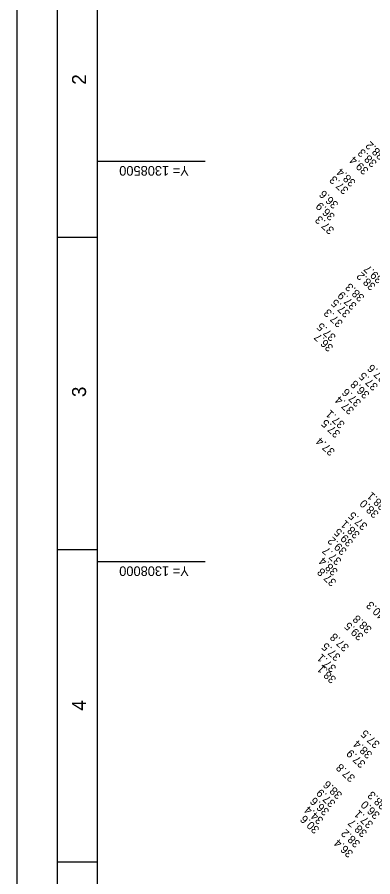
# Model space of a CAD drawing. Extents: x 515576 to 518976, y 1305110 to 1309511.
# Drawn here: x 515576 to 516021, y 1307607 to 1308680 of the extents above; entities that cross this region are included whole.
import ezdxf

# ---------------------------------------------------------------- set-up
doc = ezdxf.new("R2010")
doc.units = 0
for name, color, linetype in [('G-ANNO-NPLT', 7, 'Continuous'), ('G-ANNO-TTLB', 7, 'Continuous'), ('V-TOPO-COOR-STAT', 7, 'Continuous'), ('V-TOPO-SOUN', 7, 'Continuous')]:
    doc.layers.add(name, color=color, linetype=linetype)

msp = doc.modelspace()

# ---------------------------------------------------------------- linework, layer by layer
at = {"layer": 'G-ANNO-NPLT'}
msp.add_lwpolyline([(515576.5, 1305110.5), (515576.5, 1309510.4), (518976.4, 1309510.4), (518976.4, 1305110.5)], close=True, dxfattribs=at)
at = {"layer": 'G-ANNO-TTLB'}
for p, q in [((515626.5, 1308405.4), (515676.5, 1308405.4)), ((515626.5, 1308015.4), (515676.5, 1308015.4)), ((515626.5, 1307625.4), (515676.5, 1307625.4))]:
    msp.add_line(p, q, dxfattribs=at)
for points in [[(518926.4, 1305160.5), (518926.4, 1309460.4), (515626.5, 1309460.4), (515626.5, 1305160.5)], [(515676.5, 1309410.4), (515676.5, 1305285.5), (518876.4, 1305285.5), (518876.4, 1309410.4)]]:
    msp.add_lwpolyline(points, close=True, dxfattribs=at)
at = {"layer": 'V-TOPO-COOR-STAT'}
for p, q in [((515811.5, 1308500), (515676.5, 1308500)), ((515811.5, 1308000), (515676.5, 1308000))]:
    msp.add_line(p, q, dxfattribs=at)

# ---------------------------------------------------------------- texts
at = {"layer": 'G-ANNO-TTLB'}
for s, p in [('2', (515662.6, 1308595.9)), ('3', (515662.6, 1308205.8)), ('4', (515662.6, 1307814.1))]:
    msp.add_text(s, height=17.5, rotation=90, dxfattribs=at).set_placement(p)
at = {"layer": 'V-TOPO-COOR-STAT'}
for s, p in [('Y= 1308500', (515791.1, 1308494.3)), ('Y= 1308000', (515791.1, 1307994.3))]:
    msp.add_text(s, height=12, rotation=180, dxfattribs=at).set_placement(p)
at = {"layer": 'V-TOPO-SOUN'}
for s, p in [('38.2 ', (516036.9, 1308508.1)), ('38.3 ', (516027.2, 1308498.9)), ('39.4 ', (516016.8, 1308489.6)), ('38.4 ', (516000.7, 1308474.6)), ('37.3 ', (515991.8, 1308465.1)), ('36.6 ', (515979, 1308447.1)), ('36.9 ', (515974.8, 1308432.3)), ('37.3 ', (515973.8, 1308415.2)), ('39.7 ', (516034.7, 1308353.8)), ('38.2 ', (516025.7, 1308345.1)), ('38.3 ', (516011.6, 1308331)), ('37.9 ', (516002, 1308320.8)), ('37.5 ', (515993.8, 1308311.2)), ('37.3 ', (515984.7, 1308298.9)), ('37.5 ', (515975.9, 1308281.6)), ('36.7 ', (515972.6, 1308268.6)), ('37.6 ', (516039.2, 1308229.8)), ('37.5 ', (516028.6, 1308219.9)), ('36.8 ', (516018, 1308209.8)), ('37.6 ', (516007.5, 1308199.7)), ('37.4 ', (515998.7, 1308190.1)), ('37.1 ', (515987.1, 1308172.7)), ('37.5 ', (515981.5, 1308161)), ('37.4 ', (515974.8, 1308138.5)), ('38.1 ', (516038.7, 1308070.3)), ('38.0 ', (516029.6, 1308060.8)), ('37.5 ', (516015.4, 1308045.6)), ('38.1 ', (516005.9, 1308035)), ('39.5 ', (515997.5, 1308025)), ('39.2 ', (515989.6, 1308014.4)), ('37.7 ', (515982.9, 1308001.9)), ('38.4 ', (515978.4, 1307988.8)), ('37.8 ', (515976.5, 1307975.4)), ('40.3 ', (516037.8, 1307933.7)), ('38.8 ', (516020.9, 1307916.6)), ('39.5 ', (516010.5, 1307907.8)), ('37.8 ', (515992.4, 1307894)), ('37.5 ', (515981.9, 1307882.1)), ('37.1 ', (515976.3, 1307868.1)), ('38.1 ', (515976.3, 1307854.2)), ('37.5 ', (516030.9, 1307773.2)), ('38.4 ', (516021.5, 1307760.3)), ('37.9 ', (516013, 1307748.7)), ('37.8 ', (516000, 1307731)), ('38.6 ', (515983.9, 1307709.7)), ('37.9 ', (515975.4, 1307699.4)), ('36.6 ', (515967.6, 1307689.1)), ('38.3 ', (516039.5, 1307696.5)), ('34.4 ', (515960.3, 1307678.1)), ('36.0 ', (516031, 1307684.7)), ('30.6 ', (515955.2, 1307666.6)), ('37.1 ', (516022.6, 1307673.1)), ('38.7 ', (516015, 1307662.1)), ('38.2 ', (516006.4, 1307649.1)), ('36.4 ', (515997.5, 1307636.7))]:
    msp.add_text(s, height=10, rotation=136.9626, dxfattribs=at).set_placement(p)

doc.saveas('drawing.dxf')
